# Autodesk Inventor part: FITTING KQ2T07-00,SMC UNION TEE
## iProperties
Title: FITTING KQ2T07-00,SMC UNION TEE
Author: bnaylor
Shininess: 0.0
Length Units: 11272
Angle Units: 11286
Time Units: 11279
Mass Units: 11290
Length Display Precision: 4
Angle Display Precision: 2
Compacted: True
PropertySet Name: _Private Model Information
Created: 2001-11
Part Number: N/A
Material: Default
Document SubType Name: Modeling
Designer: bnaylor
Control State: 0
Master: False
Checked Out: False
PropertySet Name: Design Tracking Control
Density: 0.0
Volumn: 0.0
Area: 0.0
PropertySet Name: Model Information
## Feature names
1. Extrusion3
2. Extrusion4
3. Extrusion5
4. Extrusion6
5. Extrusion7
6. Extrusion8
7. Extrusion9
8. Extrusion10
9. Extrusion11
10. Extrusion12
11. Extrusion13
12. Extrusion15
13. Extrusion16
14. Extrusion17
15. Extrusion18
16. Extrusion19
